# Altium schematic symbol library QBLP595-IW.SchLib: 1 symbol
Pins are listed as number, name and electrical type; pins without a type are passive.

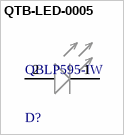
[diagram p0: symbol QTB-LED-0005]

## QTB-LED-0005
designator D?, comment QBLP595-IW
LED WHITE DIFFUSED 0402 SMD; Manufacturer: QT Brightek (QTB); Luminous Intensity: 210mcd; Viewing Angle: 150°; Forward Voltage: 3.2V; Test Current: 20mA; Lens Style: Flat; Lens Size: 0.5mm
footprint FP-QBLP595-IW-MFG
pins: 1 CATHODE (-), 2 ANODE (+)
